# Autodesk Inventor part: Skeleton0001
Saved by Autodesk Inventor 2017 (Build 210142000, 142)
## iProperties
Created: 2017-11
Part Number: Skeleton0001
Material: Generic
Document SubType Name: Modeling
Designer: iusti
Density: 1 g/cm^3
Appearance: Default
_SkeletonDoc: Frame Skeleton File
_Version: 15.0.0
Author: iusti
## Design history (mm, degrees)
sketch "Reference Skeleton"
